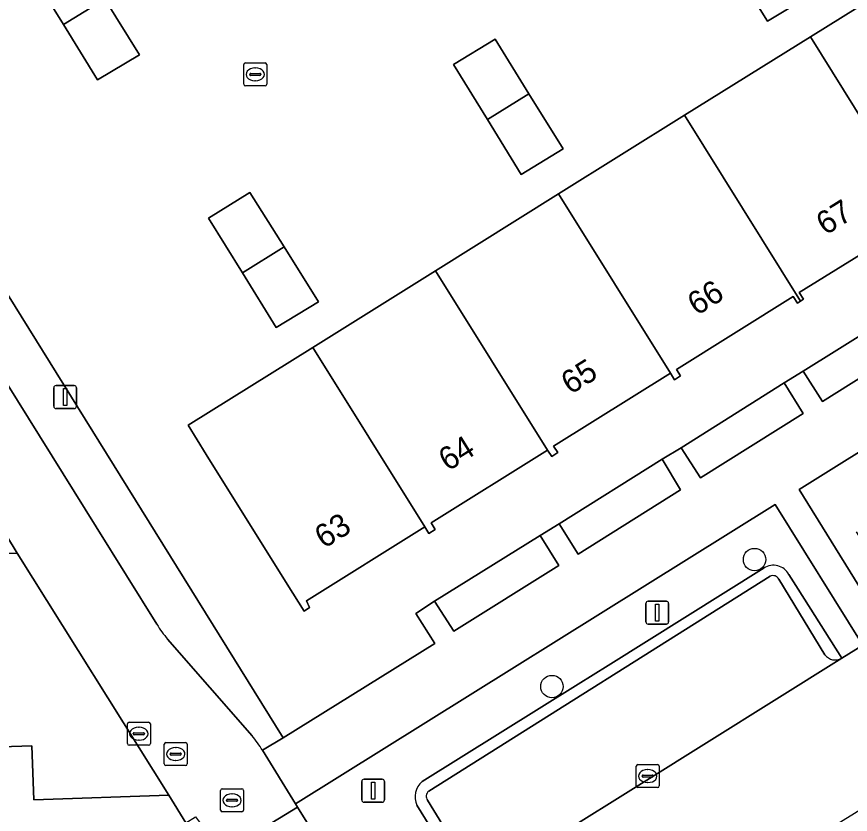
# Model space of a CAD drawing. Extents: x 159279 to 160377, y 384531 to 385888.
# Drawn here: x 159591.51 to 159627.77, y 385338.32 to 385373 of the extents above; entities that cross this region are included whole.
import ezdxf

# ---------------------------------------------------------------- set-up
doc = ezdxf.new("R2010")
doc.units = 0
for name, color, linetype in [('IMGEO_Boom', 7, 'Continuous'), ('IMGEO_Erf', 7, 'Continuous'), ('IMGEO_Groenvoorziening', 7, 'Continuous'), ('IMGEO_Kolk', 7, 'Continuous'), ('IMGEO_Lichtmast', 7, 'Continuous'), ('IMGEO_Pand', 7, 'Continuous'), ('IMGEO_Pand_nummerreeks', 7, 'Continuous'), ('IMGEO_Parkeervlak_open', 7, 'Continuous'), ('IMGEO_Rijbaan_lokaal_open', 7, 'Continuous'), ('IMGEO_Rioolput', 7, 'Continuous'), ('IMGEO_Voetpad_open', 7, 'Continuous')]:
    doc.layers.add(name, color=color, linetype=linetype)

msp = doc.modelspace()

# ---------------------------------------------------------------- linework, layer by layer
at = {"layer": 'IMGEO_Boom'}
for centre in [(159623.61, 385349.393), (159614.795, 385343.87)]:
    msp.add_circle(centre, 0.489, dxfattribs=at)
at = {"layer": 'IMGEO_Erf'}
for points in [[(159578.171, 385381.737), (159603.097, 385341.65), (159609.696, 385345.751), (159608.873, 385347.054), (159609.689, 385347.581), (159614.284, 385350.439), (159615.108, 385350.946), (159619.584, 385353.761), (159620.414, 385354.258), (159624.892, 385357.078), (159625.716, 385357.591), (159630.342, 385360.469), (159631.16, 385360.972), (159635.642, 385363.77), (159636.446, 385364.289), (159641.073, 385367.168), (159641.907, 385367.672), (159644.262, 385369.162), (159645.11, 385369.682), (159651.078, 385373.423)], [(159630.638, 385364.156), (159625.555, 385361.001), (159625.74, 385360.722), (159625.607, 385360.631), (159625.471, 385360.537), (159625.285, 385360.831), (159620.216, 385357.658), (159620.393, 385357.386), (159620.131, 385357.209), (159619.95, 385357.493), (159614.868, 385354.325), (159615.046, 385354.044), (159614.784, 385353.872), (159614.598, 385354.15), (159609.538, 385350.989), (159609.712, 385350.709), (159609.44, 385350.535), (159609.263, 385350.813), (159604.11, 385347.605), (159604.246, 385347.31), (159604.01, 385347.149), (159603.277, 385348.324), (159599.755, 385353.97), (159598.966, 385355.235), (159604.39, 385358.62), (159609.728, 385361.952), (159615.082, 385365.293), (159620.562, 385368.714), (159626.037, 385372.131), (159631.377, 385375.464)]]:
    msp.add_lwpolyline(points, dxfattribs=at)
for points in [[(159621.216, 385377.554), (159623.026, 385378.681), (159624.512, 385376.31), (159626.009, 385373.922), (159624.169, 385372.804), (159622.693, 385375.179)], [(159595.337, 385373.771), (159596.844, 385371.345), (159595.031, 385370.248), (159593.539, 385372.658), (159592.047, 385375.067), (159593.841, 385376.178)], [(159613.795, 385369.647), (159615.281, 385367.252), (159613.454, 385366.145), (159611.984, 385368.53), (159610.513, 385370.915), (159612.326, 385372.016)], [(159603.144, 385362.991), (159604.641, 385360.603), (159602.801, 385359.485), (159601.325, 385361.86), (159599.848, 385364.235), (159601.658, 385365.362)]]:
    msp.add_lwpolyline(points, close=True, dxfattribs=at)
at = {"layer": 'IMGEO_Groenvoorziening'}
for points in [[(159644.2, 385360.668), (159646.475, 385356.966), (159647.441, 385357.57), (159643.591, 385363.703), (159625.552, 385352.435), (159629.355, 385346.306), (159630.352, 385346.921), (159628.039, 385350.599)], [(159587.601, 385349.567), (159591.531, 385349.672), (159590.116, 385351.973)], [(159625.098, 385348.751), (159625.499, 385348.113), (159627.402, 385345.101), (159628.319, 385345.666), (159624.51, 385351.792), (159603.631, 385338.78), (159603.728, 385338.622), (159605.845, 385335.24)], [(159609.152, 385339.74), (159615.941, 385343.971), (159617.237, 385344.788), (159624.021, 385349.029)], [(159588.331, 385331.359), (159598.867, 385337.949), (159598.131, 385339.143), (159592.247, 385338.952), (159592.174, 385341.298), (159590.849, 385341.253)], [(159609.941, 385334.203), (159611.219, 385334.995), (159608.92, 385338.708)]]:
    msp.add_lwpolyline(points, dxfattribs=at)
for points in [[(159630.342, 385360.469), (159625.716, 385357.591), (159626.565, 385356.272), (159631.157, 385359.15)], [(159624.892, 385357.078), (159620.414, 385354.258), (159621.251, 385352.954), (159625.727, 385355.752)], [(159619.584, 385353.761), (159615.108, 385350.946), (159615.938, 385349.636), (159620.38, 385352.427)], [(159614.284, 385350.439), (159609.689, 385347.581), (159610.524, 385346.283), (159615.099, 385349.139)]]:
    msp.add_lwpolyline(points, close=True, dxfattribs=at)
for centre, radius, start, end in [((159624.429, 385348.383), 0.764, 28.8026, 122.2504), ((159609.708, 385339.073), 0.869, 129.8298, 204.8305)]:
    msp.add_arc(centre, radius, start, end, dxfattribs=at)
at = {"layer": 'IMGEO_Kolk'}
for p, q in [((159601.387, 385370.065), (159601.387, 385370.917)), ((159601.462, 385370.991), (159602.314, 385370.991)), ((159602.388, 385370.917), (159602.388, 385370.065)), ((159601.689, 385370.534), (159602.087, 385370.534)), ((159601.875, 385370.771), (159601.9, 385370.771)), ((159601.646, 385370.485), (159601.646, 385370.497)), ((159602.084, 385370.448), (159601.686, 385370.448)), ((159601.898, 385370.211), (159601.873, 385370.211)), ((159602.13, 385370.497), (159602.13, 385370.485)), ((159602.314, 385369.991), (159601.462, 385369.991)), ((159596.322, 385341.395), (159596.322, 385342.247)), ((159596.397, 385342.321), (159597.249, 385342.321)), ((159597.323, 385342.247), (159597.323, 385341.395)), ((159596.81, 385342.101), (159596.835, 385342.101)), ((159596.581, 385341.815), (159596.581, 385341.827)), ((159597.019, 385341.778), (159596.621, 385341.778)), ((159596.624, 385341.864), (159597.022, 385341.864)), ((159596.833, 385341.541), (159596.808, 385341.541)), ((159597.065, 385341.827), (159597.065, 385341.815)), ((159597.249, 385341.321), (159596.397, 385341.321)), ((159618.534, 385340.48), (159619.386, 385340.48)), ((159618.459, 385339.554), (159618.459, 385340.406)), ((159618.947, 385340.26), (159618.972, 385340.26)), ((159619.46, 385340.406), (159619.46, 385339.554)), ((159618.718, 385339.974), (159618.718, 385339.986)), ((159619.156, 385339.937), (159618.758, 385339.937)), ((159618.761, 385340.023), (159619.159, 385340.023)), ((159618.97, 385339.7), (159618.945, 385339.7)), ((159619.202, 385339.986), (159619.202, 385339.974)), ((159619.386, 385339.48), (159618.534, 385339.48))]:
    msp.add_line(p, q, dxfattribs=at)
for points in [[(159601.387, 385370.065), (159601.387, 385370.917)], [(159601.462, 385370.991), (159602.314, 385370.991)], [(159602.388, 385370.917), (159602.388, 385370.065)], [(159602.314, 385369.991), (159601.462, 385369.991)], [(159596.322, 385341.395), (159596.322, 385342.247)], [(159596.397, 385342.321), (159597.249, 385342.321)], [(159597.323, 385342.247), (159597.323, 385341.395)], [(159597.249, 385341.321), (159596.397, 385341.321)], [(159618.534, 385340.48), (159619.386, 385340.48)], [(159618.459, 385339.554), (159618.459, 385340.406)], [(159619.46, 385340.406), (159619.46, 385339.554)], [(159619.386, 385339.48), (159618.534, 385339.48)]]:
    msp.add_lwpolyline(points, dxfattribs=at)
for centre, radius, start, end in [((159601.464, 385370.915), 0.0765, 91.552, 178.448), ((159601.464, 385370.915), 0.0765, 91.552, 178.448), ((159602.312, 385370.915), 0.0765, 1.552, 88.448), ((159602.312, 385370.915), 0.0765, 1.552, 88.448), ((159601.686, 385370.494), 0.0403, 85.8775, 175.7526), ((159602.091, 385370.496), 0.0386, 1.7309, 96.639), ((159601.683, 385370.484), 0.0366, 178.938, 274.7102), ((159602.087, 385370.491), 0.043, 264.8664, 352.4533), ((159601.464, 385370.067), 0.0765, 181.552, 268.448), ((159601.464, 385370.067), 0.0765, 181.552, 268.448), ((159602.312, 385370.067), 0.0765, 271.552, 358.448), ((159602.312, 385370.067), 0.0765, 271.552, 358.448), ((159596.399, 385342.245), 0.0765, 91.552, 178.448), ((159596.399, 385342.245), 0.0765, 91.552, 178.448), ((159597.247, 385342.245), 0.0765, 1.552, 88.448), ((159597.247, 385342.245), 0.0765, 1.552, 88.448), ((159596.621, 385341.824), 0.0403, 85.8775, 175.7526), ((159596.618, 385341.814), 0.0366, 178.938, 274.7102), ((159597.022, 385341.821), 0.043, 264.8664, 352.4533), ((159597.026, 385341.826), 0.0386, 1.7309, 96.639), ((159596.399, 385341.397), 0.0765, 181.552, 268.448), ((159596.399, 385341.397), 0.0765, 181.552, 268.448), ((159597.247, 385341.397), 0.0765, 271.552, 358.448), ((159597.247, 385341.397), 0.0765, 271.552, 358.448), ((159618.536, 385340.404), 0.0765, 91.552, 178.448), ((159618.536, 385340.404), 0.0765, 91.552, 178.448), ((159619.384, 385340.404), 0.0765, 1.552, 88.448), ((159619.384, 385340.404), 0.0765, 1.552, 88.448), ((159618.758, 385339.983), 0.0403, 85.8775, 175.7526), ((159618.755, 385339.973), 0.0366, 178.938, 274.7102), ((159619.159, 385339.98), 0.043, 264.8664, 352.4533), ((159619.163, 385339.985), 0.0386, 1.7309, 96.639), ((159618.536, 385339.556), 0.0765, 181.552, 268.448), ((159618.536, 385339.556), 0.0765, 181.552, 268.448), ((159619.384, 385339.556), 0.0765, 271.552, 358.448), ((159619.384, 385339.556), 0.0765, 271.552, 358.448)]:
    msp.add_arc(centre, radius, start, end, dxfattribs=at)
for centre, major_axis, ratio, start_param, end_param in [((159601.874, 385370.491), (-0.387, 0.002), 0.722429, 4.712389, 7.853982), ((159601.899, 385370.491), (-0.39, 0.002), 0.717154, 1.570796, 4.712389), ((159596.809, 385341.821), (-0.387, 0.002), 0.722429, 4.712389, 7.853982), ((159596.834, 385341.821), (-0.39, 0.002), 0.717154, 1.570796, 4.712389), ((159618.946, 385339.98), (-0.387, 0.002), 0.722429, 4.712389, 7.853982), ((159618.971, 385339.98), (-0.39, 0.002), 0.717154, 1.570796, 4.712389)]:
    msp.add_ellipse(centre, major_axis=major_axis, ratio=ratio, start_param=start_param, end_param=end_param, dxfattribs=at)
at = {"layer": 'IMGEO_Lichtmast'}
for p, q in [((159593.12, 385356.062), (159593.12, 385356.862)), ((159593.12, 385356.862), (159593.12, 385356.062)), ((159593.22, 385356.962), (159594.01, 385356.962)), ((159594.01, 385356.962), (159593.22, 385356.962)), ((159594.11, 385356.862), (159594.11, 385356.062)), ((159594.11, 385356.062), (159594.11, 385356.862)), ((159594.01, 385355.962), (159593.22, 385355.962)), ((159593.22, 385355.962), (159594.01, 385355.962)), ((159618.881, 385346.686), (159618.881, 385347.486)), ((159618.881, 385347.486), (159618.881, 385346.686)), ((159618.981, 385347.586), (159619.771, 385347.586)), ((159619.771, 385347.586), (159618.981, 385347.586)), ((159619.871, 385347.486), (159619.871, 385346.686)), ((159619.871, 385346.686), (159619.871, 385347.486)), ((159619.771, 385346.586), (159618.981, 385346.586)), ((159618.981, 385346.586), (159619.771, 385346.586)), ((159606.518, 385338.944), (159606.518, 385339.744)), ((159606.518, 385339.744), (159606.518, 385338.944)), ((159606.618, 385339.844), (159607.408, 385339.844)), ((159607.408, 385339.844), (159606.618, 385339.844)), ((159607.508, 385339.744), (159607.508, 385338.944)), ((159607.508, 385338.944), (159607.508, 385339.744)), ((159607.408, 385338.844), (159606.618, 385338.844)), ((159606.618, 385338.844), (159607.408, 385338.844))]:
    msp.add_line(p, q, dxfattribs=at)
for points in [[(159593.54, 385356.837), (159593.69, 385356.837), (159593.69, 385356.087), (159593.54, 385356.087), (159593.54, 385356.837)], [(159619.301, 385347.461), (159619.451, 385347.461), (159619.451, 385346.711), (159619.301, 385346.711), (159619.301, 385347.461)], [(159606.938, 385339.719), (159607.088, 385339.719), (159607.088, 385338.969), (159606.938, 385338.969), (159606.938, 385339.719)]]:
    msp.add_lwpolyline(points, dxfattribs=at)
for centre, start, end in [((159593.22, 385356.862), 90, 180), ((159593.22, 385356.862), 90, 180), ((159594.01, 385356.862), 0, 90), ((159594.01, 385356.862), 360, 90), ((159593.22, 385356.062), 180, 270), ((159593.22, 385356.062), 180, 270), ((159594.01, 385356.062), 270, 0), ((159594.01, 385356.062), 270, 0), ((159618.981, 385347.486), 90, 180), ((159618.981, 385347.486), 90, 180), ((159619.771, 385347.486), 0, 90), ((159619.771, 385347.486), 360, 90), ((159618.981, 385346.686), 180, 270), ((159618.981, 385346.686), 180, 270), ((159619.771, 385346.686), 270, 0), ((159619.771, 385346.686), 270, 0), ((159606.618, 385339.744), 90, 180), ((159606.618, 385339.744), 90, 180), ((159607.408, 385339.744), 0, 90), ((159607.408, 385339.744), 360, 90), ((159606.618, 385338.944), 180, 270), ((159606.618, 385338.944), 180, 270), ((159607.408, 385338.944), 270, 0), ((159607.408, 385338.944), 270, 0)]:
    msp.add_arc(centre, 0.1, start, end, dxfattribs=at)
at = {"layer": 'IMGEO_Pand'}
for points in [[(159592.047, 385375.067), (159593.539, 385372.658), (159595.337, 385373.771), (159593.841, 385376.178)], [(159624.512, 385376.31), (159622.693, 385375.179), (159624.169, 385372.804), (159626.009, 385373.922)], [(159631.377, 385375.464), (159626.037, 385372.131), (159630.905, 385364.331), (159635.966, 385367.482), (159636.159, 385367.202), (159636.415, 385367.385), (159636.246, 385367.663)], [(159595.337, 385373.771), (159593.539, 385372.658), (159595.031, 385370.248), (159596.844, 385371.345)], [(159610.513, 385370.915), (159611.984, 385368.53), (159613.795, 385369.647), (159612.326, 385372.016)], [(159626.037, 385372.131), (159620.562, 385368.714), (159625.607, 385360.631), (159625.74, 385360.722), (159625.555, 385361.001), (159630.638, 385364.156), (159630.817, 385363.876), (159631.078, 385364.052), (159630.905, 385364.331)], [(159613.795, 385369.647), (159611.984, 385368.53), (159613.454, 385366.145), (159615.281, 385367.252)], [(159620.562, 385368.714), (159615.082, 385365.293), (159619.95, 385357.493), (159620.131, 385357.209), (159620.393, 385357.386), (159620.216, 385357.658), (159625.285, 385360.831), (159625.471, 385360.537), (159625.607, 385360.631)], [(159599.848, 385364.235), (159601.325, 385361.86), (159603.144, 385362.991), (159601.658, 385365.362)], [(159615.082, 385365.293), (159609.728, 385361.952), (159614.598, 385354.15), (159614.784, 385353.872), (159615.046, 385354.044), (159614.868, 385354.325), (159619.95, 385357.493)], [(159603.144, 385362.991), (159601.325, 385361.86), (159602.801, 385359.485), (159604.641, 385360.603)], [(159609.728, 385361.952), (159604.39, 385358.62), (159609.263, 385350.813), (159609.44, 385350.535), (159609.712, 385350.709), (159609.538, 385350.989), (159614.598, 385354.15)], [(159604.39, 385358.62), (159598.966, 385355.235), (159599.755, 385353.97), (159603.277, 385348.324), (159604.01, 385347.149), (159604.246, 385347.31), (159604.11, 385347.605), (159609.263, 385350.813)]]:
    msp.add_lwpolyline(points, close=True, dxfattribs=at)
at = {"layer": 'IMGEO_Parkeervlak_open'}
msp.add_lwpolyline([(159591.531, 385349.672), (159587.601, 385349.567), (159587.706, 385346.263), (159589.165, 385346.303), (159589.23, 385343.758), (159590.79, 385343.791), (159590.849, 385341.253), (159592.174, 385341.298), (159592.247, 385338.952), (159598.131, 385339.143)], close=True, dxfattribs=at)
for points in [[(159624.284, 385348.67), (159609.823, 385339.569), (159609.442, 385339.325)], [(159626.669, 385345.257), (159624.662, 385348.536)], [(159611.219, 385334.995), (159611.352, 385335.08), (159618.688, 385339.659), (159627.402, 385345.101)], [(159609.38, 385338.929), (159611.379, 385335.677)]]:
    msp.add_lwpolyline(points, dxfattribs=at)
for centre, radius, start, end in [((159624.406, 385348.414), 0.283, 25.4077, 115.5538), ((159627.124, 385345.594), 0.566, 216.5659, 299.4048), ((159609.6, 385339.097), 0.277, 124.6969, 217.5065)]:
    msp.add_arc(centre, radius, start, end, dxfattribs=at)
at = {"layer": 'IMGEO_Rijbaan_lokaal_open'}
for points in [[(159597.608, 385346.585), (159594.972, 385350.822), (159574.018, 385384.446)], [(159571.683, 385381.626), (159573.925, 385378.018), (159575.546, 385375.339), (159582.127, 385364.81), (159583.549, 385362.552), (159590.116, 385351.973), (159591.531, 385349.672), (159598.131, 385339.143), (159598.867, 385337.949), (159599.289, 385338.209), (159600.372, 385336.757), (159600.453, 385336.627), (159603.728, 385338.622), (159603.631, 385338.78), (159602.195, 385341.102)], [(159647.441, 385357.57), (159646.475, 385356.966), (159641.141, 385353.643), (159637.039, 385351.087), (159630.352, 385346.921), (159629.355, 385346.306), (159628.319, 385345.666), (159627.402, 385345.101), (159618.688, 385339.659), (159611.352, 385335.08), (159614.419, 385330.007), (159640.215, 385345.938), (159644.265, 385348.476), (159693.538, 385379.269)], [(159601.75, 385341.73), (159598.074, 385345.933)], [(159605.845, 385335.24), (159603.728, 385338.622), (159600.453, 385336.627), (159601.016, 385335.722), (159603.181, 385332.247)]]:
    msp.add_lwpolyline(points, dxfattribs=at)
for centre, radius, start, end in [((159601.385, 385348.792), 4.375, 210.2988, 220.8098), ((159598.078, 385338.656), 4.789, 30.7119, 39.9308)]:
    msp.add_arc(centre, radius, start, end, dxfattribs=at)
at = {"layer": 'IMGEO_Rioolput'}
for p, q in [((159597.927, 385340.511), (159597.927, 385341.363)), ((159598.002, 385341.437), (159598.854, 385341.437)), ((159598.415, 385341.217), (159598.44, 385341.217)), ((159598.928, 385341.363), (159598.928, 385340.511)), ((159598.186, 385340.931), (159598.186, 385340.943)), ((159598.624, 385340.894), (159598.226, 385340.894)), ((159598.229, 385340.98), (159598.627, 385340.98)), ((159598.67, 385340.943), (159598.67, 385340.931)), ((159598.854, 385340.437), (159598.002, 385340.437)), ((159598.438, 385340.657), (159598.413, 385340.657)), ((159600.376, 385338.5), (159600.376, 385339.352)), ((159600.451, 385339.426), (159601.303, 385339.426)), ((159601.377, 385339.352), (159601.377, 385338.5)), ((159600.678, 385338.969), (159601.076, 385338.969)), ((159600.864, 385339.206), (159600.889, 385339.206)), ((159600.635, 385338.92), (159600.635, 385338.932)), ((159601.073, 385338.883), (159600.675, 385338.883)), ((159600.887, 385338.646), (159600.862, 385338.646)), ((159601.119, 385338.932), (159601.119, 385338.92)), ((159601.303, 385338.426), (159600.451, 385338.426))]:
    msp.add_line(p, q, dxfattribs=at)
for points in [[(159597.927, 385340.511), (159597.927, 385341.363)], [(159598.002, 385341.437), (159598.854, 385341.437)], [(159598.928, 385341.363), (159598.928, 385340.511)], [(159598.854, 385340.437), (159598.002, 385340.437)], [(159600.376, 385338.5), (159600.376, 385339.352)], [(159600.451, 385339.426), (159601.303, 385339.426)], [(159601.377, 385339.352), (159601.377, 385338.5)], [(159601.303, 385338.426), (159600.451, 385338.426)]]:
    msp.add_lwpolyline(points, dxfattribs=at)
for centre, radius, start, end in [((159598.004, 385341.361), 0.0765, 91.552, 178.448), ((159598.004, 385341.361), 0.0765, 91.552, 178.448), ((159598.852, 385341.361), 0.0765, 1.552, 88.448), ((159598.852, 385341.361), 0.0765, 1.552, 88.448), ((159598.226, 385340.94), 0.0403, 85.8775, 175.7526), ((159598.223, 385340.93), 0.0366, 178.938, 274.7102), ((159598.627, 385340.937), 0.043, 264.8664, 352.4533), ((159598.631, 385340.942), 0.0386, 1.7309, 96.639), ((159598.004, 385340.513), 0.0765, 181.552, 268.448), ((159598.004, 385340.513), 0.0765, 181.552, 268.448), ((159598.852, 385340.513), 0.0765, 271.552, 358.448), ((159598.852, 385340.513), 0.0765, 271.552, 358.448), ((159600.453, 385339.35), 0.0765, 91.552, 178.448), ((159600.453, 385339.35), 0.0765, 91.552, 178.448), ((159601.301, 385339.35), 0.0765, 1.552, 88.448), ((159601.301, 385339.35), 0.0765, 1.552, 88.448), ((159600.675, 385338.929), 0.0403, 85.8775, 175.7526), ((159601.08, 385338.931), 0.0386, 1.7309, 96.639), ((159600.672, 385338.919), 0.0366, 178.938, 274.7102), ((159601.076, 385338.926), 0.043, 264.8664, 352.4533), ((159600.453, 385338.502), 0.0765, 181.552, 268.448), ((159600.453, 385338.502), 0.0765, 181.552, 268.448), ((159601.301, 385338.502), 0.0765, 271.552, 358.448), ((159601.301, 385338.502), 0.0765, 271.552, 358.448)]:
    msp.add_arc(centre, radius, start, end, dxfattribs=at)
for centre, major_axis, ratio, start_param, end_param in [((159598.414, 385340.937), (-0.387, 0.002), 0.722429, 4.712389, 7.853982), ((159598.439, 385340.937), (-0.39, 0.002), 0.717154, 1.570796, 4.712389), ((159600.863, 385338.926), (-0.387, 0.002), 0.722429, 4.712389, 7.853982), ((159600.888, 385338.926), (-0.39, 0.002), 0.717154, 1.570796, 4.712389)]:
    msp.add_ellipse(centre, major_axis=major_axis, ratio=ratio, start_param=start_param, end_param=end_param, dxfattribs=at)
at = {"layer": 'IMGEO_Voetpad_open'}
for points in [[(159574.018, 385384.446), (159594.972, 385350.822), (159597.608, 385346.585)], [(159602.195, 385341.102), (159603.097, 385341.65), (159578.171, 385381.737)], [(159629.355, 385346.306), (159625.552, 385352.435), (159643.591, 385363.703)], [(159631.157, 385359.15), (159626.565, 385356.272), (159625.716, 385357.591), (159624.892, 385357.078), (159625.727, 385355.752), (159621.251, 385352.954), (159620.414, 385354.258), (159619.584, 385353.761), (159620.38, 385352.427), (159615.938, 385349.636), (159615.108, 385350.946), (159614.284, 385350.439), (159615.099, 385349.139), (159610.524, 385346.283), (159609.689, 385347.581), (159608.873, 385347.054), (159609.696, 385345.751), (159603.097, 385341.65), (159602.195, 385341.102), (159603.631, 385338.78), (159624.51, 385351.792), (159628.319, 385345.666)], [(159624.021, 385349.029), (159617.237, 385344.788), (159615.941, 385343.971), (159609.152, 385339.74)], [(159609.442, 385339.325), (159609.823, 385339.569), (159624.284, 385348.67)], [(159624.662, 385348.536), (159626.669, 385345.257)], [(159627.402, 385345.101), (159625.499, 385348.113), (159625.098, 385348.751)], [(159598.074, 385345.933), (159601.75, 385341.73)], [(159608.92, 385338.708), (159611.219, 385334.995)], [(159611.379, 385335.677), (159609.38, 385338.929)]]:
    msp.add_lwpolyline(points, dxfattribs=at)
for centre, radius, start, end in [((159624.429, 385348.383), 0.764, 28.8026, 122.2504), ((159624.406, 385348.414), 0.283, 25.4077, 115.5538), ((159601.385, 385348.792), 4.375, 210.2988, 220.8098), ((159627.124, 385345.594), 0.566, 216.5659, 299.4048), ((159598.078, 385338.656), 4.789, 30.7119, 39.9308), ((159609.708, 385339.073), 0.869, 129.8298, 204.8305), ((159609.6, 385339.097), 0.277, 124.6969, 217.5065)]:
    msp.add_arc(centre, radius, start, end, dxfattribs=at)

# ---------------------------------------------------------------- texts
at = {"layer": 'IMGEO_Pand_nummerreeks'}
for s, rotation, p in [('67', 31.8278, (159626.691, 385363.472)), ('66', 32.0455, (159621.097, 385359.979)), ('65', 31.9367, (159615.597, 385356.547)), ('64', 31.994, (159610.266, 385353.212)), ('63', 31.9023, (159604.875, 385349.848))]:
    msp.add_text(s, height=1, rotation=rotation, dxfattribs=at).set_placement(p)

doc.saveas('drawing.dxf')
